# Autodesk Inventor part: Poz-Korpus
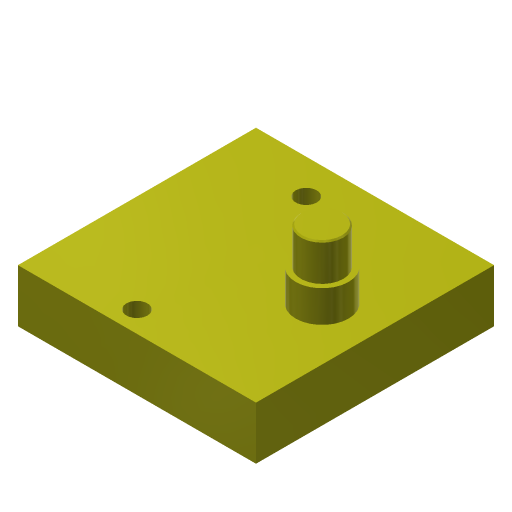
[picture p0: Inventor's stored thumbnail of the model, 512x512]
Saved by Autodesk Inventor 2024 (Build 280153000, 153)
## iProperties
Company: ATC
Shininess: 20.0
Angle Display Precision: 2
Document Length Units: 11269
Document Angle Units: 11279
Document Time Units: 11290
Document Mass Units: 11283
Document Length Units Precision: 3
Document Angle Units Precision: 2
Created: 2023-03
Part Number: Poz-Korpus
Material: Standardowy
Document SubType Name: Modelowanie
Designer: Andrzej Jaskulski
Density: 1 g/cm^3
Appearance: Żółta
Checked By: A.J.
Engr Approved By: Andrzej Jaskulski
Mfg Approved By: Andrzej Jaskulski
Authority: A.J.
Density: 0.0
Volumn: 0.0
Area: 0.0
PropertySet Name: Model Information
Control State: 0
Master: False
Checked Out: False
Title: A.J.: Kurs R2024-MEP
Author: Andrzej Jaskulski
Revision Number: 1/24
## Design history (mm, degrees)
sketch "Szkic1"
  geometry: L1 (0, 90)-(90, 90); L2 (0, 0)-(90, 0); L3 (90, 0)-(90, 90); L4 (0, 90)-(0, 0); C1 r 4 at (32, 77); C2 r 4 at (37, 8); C3 r 10 at (70, 45); A1 r 40 centre (70, 45) between (45, 76.225) and (45, 13.775); 3 further points
  constraints: 8 end point, 4 centre point, 3 midpoint, 3 vertical alignment, 2 point on circle, 1 coincident, 1 horizontal, 1 horizontal alignment, 1 perpendicular, 1 vertical, 1 other
  dimensions: "d9" = 8 diameter of C1 (= d6); "d10" = 8 diameter of C2 (= d6); "d22" = 40 radius of A1; "d25" = 20 diameter of C3 (= d0); "d26" = 20 distance from line of A1.centre L3; "d56" = 13 distance from line of L1 C1.centre; "d57" = 8 distance from line of C2.centre L2; "d66" = 90 distance of L1.start L1.end; "d67" = 90 distance of L2.end L1.end; "d68" = 32 distance from line of L4 C1.centre; "d69" = 37 distance from line of C2.centre L4
extrude "Wyciągnięcie proste2" join sketch "Szkic1" distance "d27" = 12; taper "d28" = 0 deg
sketch "Szkic2"
  geometry: C1 r 10 at (0, 0) reference; C2 r 8 at (0, 0)
  constraints: 1 centre point, 1 coincident
  dimensions: "d34" = 2 radial gap between concentric circles of C2 C1
extrude "Wyciągnięcie proste3" join sketch "Szkic2" distance "d35" = 14; taper "d36" = 0 deg
chamfer "Faza1" distance "d39" = 0.5; stored, may be unused: second distance "d40" = 0.5, angle "d64" = 45 deg
node "Płaszczyzna konstrukcyjna3"
sketch "Tory Suwaków"
  geometry: L1 (-146.589, -25)-(110, -25); L2 (110, -25)-(110, 190.954); L3 (90, 90)-(90, 0) reference; L4 (90, 0)-(0, 0) reference
  constraints: 4 end point, 1 horizontal
  dimensions: "d63" = 20 distance between parallel lines of L3 L2; "d70" = 25 distance between parallel lines of L4 L1
node "Bryła1"
node "Początek"
  node "Płaszczyzna YZ"
  node "Płaszczyzna XZ"
  node "Płaszczyzna XY"
  node "Oś X"
  node "Oś Y"
  node "Oś Z"
extrude "Wyciągnięcie proste1" new body sketch "Szkic1" distance "d1" = 20; taper "d2" = 0 deg
node "Korpusy bryłowe"
node "Korpusy powierzchniowe"
node "Punkt środkowy"
other parameters: "d0" = 20, "d6" = 8, "d32" = 0, "d33" = 0, "d50" = 6
